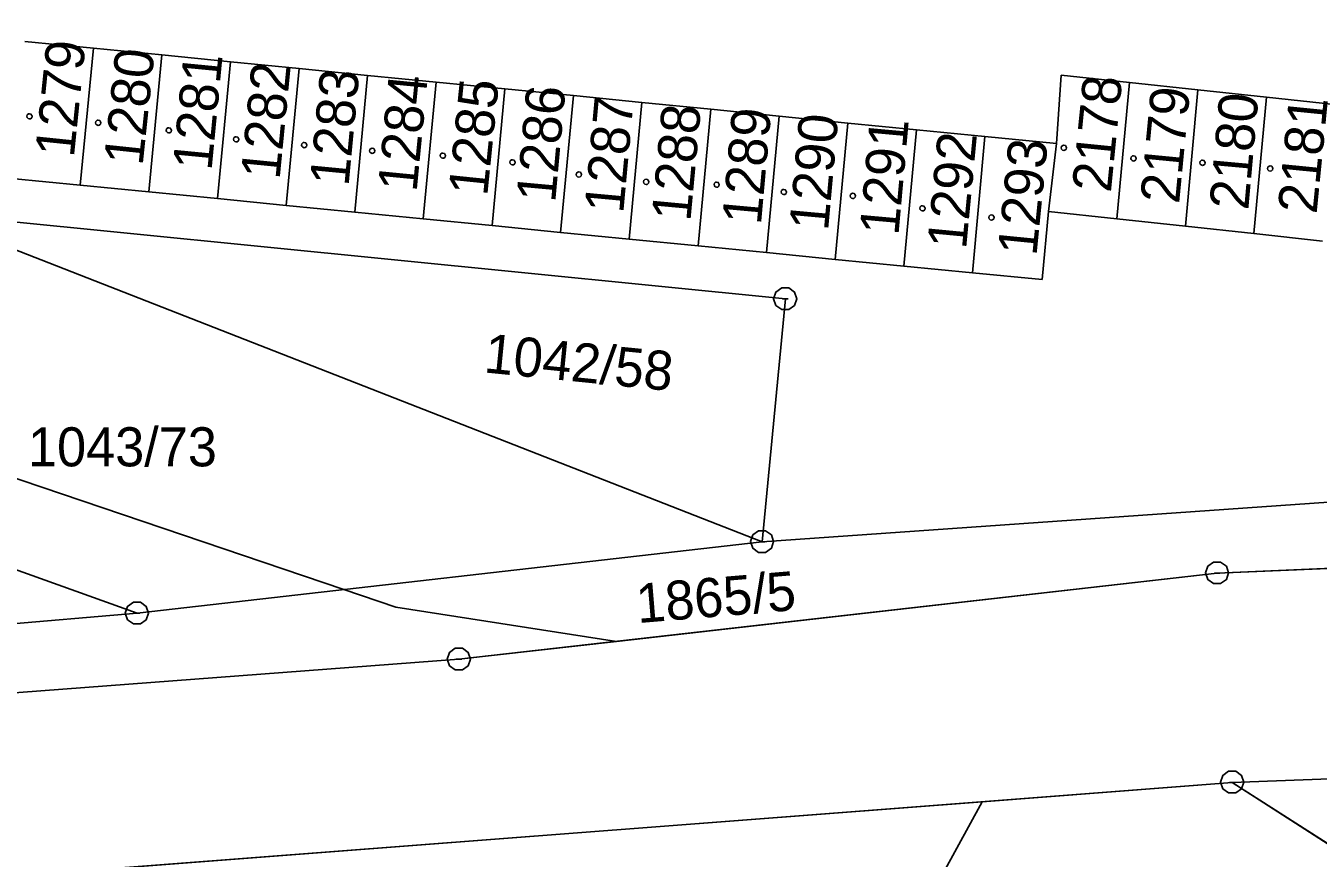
# Model space of a CAD drawing. Extents: x -777309 to -774195, y -1144706 to -1143600.
# Drawn here: x -775189.8 to -775133.6, y -1144462.3 to -1144426.1 of the extents above; entities that cross this region are included whole.
import ezdxf

# ---------------------------------------------------------------- set-up
doc = ezdxf.new("R2010")
doc.units = 0
for name, color, linetype in [('1', 7, 'Continuous'), ('11', 7, 'Continuous'), ('12', 7, 'Continuous'), ('2', 7, 'Continuous'), ('5', 7, 'Continuous'), ('8', 7, 'Continuous')]:
    doc.layers.add(name, color=color, linetype=linetype)

msp = doc.modelspace()

# ---------------------------------------------------------------- linework, layer by layer
at = {"layer": '1'}
for p, q in [((-775186.89, -1144427.09), (-775189.87, -1144426.79)), ((-775186.89, -1144427.09), (-775187.46, -1144433.05)), ((-775183.91, -1144427.38), (-775186.89, -1144427.09)), ((-775184.48, -1144433.34), (-775183.91, -1144427.38)), ((-775180.92, -1144427.68), (-775183.91, -1144427.38)), ((-775180.92, -1144427.68), (-775181.49, -1144433.63)), ((-775177.94, -1144427.97), (-775180.92, -1144427.68)), ((-775178.51, -1144433.92), (-775177.94, -1144427.97)), ((-775174.96, -1144428.27), (-775177.94, -1144427.97)), ((-775174.96, -1144428.27), (-775175.52, -1144434.22)), ((-775171.98, -1144428.56), (-775174.96, -1144428.27)), ((-775172.54, -1144434.51), (-775171.98, -1144428.56)), ((-775168.99, -1144428.86), (-775171.98, -1144428.56)), ((-775145, -1144431.23), (-775144.8, -1144428.26)), ((-775144.8, -1144428.26), (-775141.82, -1144428.58)), ((-775141.82, -1144428.58), (-775142.37, -1144434.51)), ((-775141.82, -1144428.58), (-775138.85, -1144428.9)), ((-775168.99, -1144428.86), (-775169.55, -1144434.8)), ((-775166.01, -1144429.15), (-775168.99, -1144428.86)), ((-775166.57, -1144435.1), (-775166.01, -1144429.15)), ((-775163.03, -1144429.45), (-775166.01, -1144429.15)), ((-775139.39, -1144434.83), (-775138.85, -1144428.9)), ((-775138.85, -1144428.9), (-775135.87, -1144429.22)), ((-775135.87, -1144429.22), (-775136.41, -1144435.15)), ((-775135.87, -1144429.22), (-775132.9, -1144429.54)), ((-775163.03, -1144429.45), (-775163.58, -1144435.39)), ((-775160.04, -1144429.74), (-775163.03, -1144429.45)), ((-775160.59, -1144435.68), (-775160.04, -1144429.74)), ((-775157.06, -1144430.04), (-775160.04, -1144429.74)), ((-775157.06, -1144430.04), (-775157.61, -1144435.97)), ((-775154.08, -1144430.34), (-775157.06, -1144430.04)), ((-775154.62, -1144436.27), (-775154.08, -1144430.34)), ((-775151.09, -1144430.63), (-775154.08, -1144430.34)), ((-775151.09, -1144430.63), (-775151.64, -1144436.56)), ((-775148.11, -1144430.93), (-775151.09, -1144430.63)), ((-775148.65, -1144436.85), (-775148.11, -1144430.93)), ((-775145, -1144431.23), (-775148.11, -1144430.93)), ((-775145.35, -1144434.19), (-775145, -1144431.23)), ((-775190.45, -1144432.75), (-775187.46, -1144433.05)), ((-775187.46, -1144433.05), (-775184.48, -1144433.34)), ((-775184.48, -1144433.34), (-775181.49, -1144433.63)), ((-775181.49, -1144433.63), (-775178.51, -1144433.92)), ((-775194.42, -1144434.23), (-775156.79, -1144437.99)), ((-775157.8, -1144448.55), (-775194.42, -1144434.23)), ((-775178.51, -1144433.92), (-775175.52, -1144434.22)), ((-775175.52, -1144434.22), (-775172.54, -1144434.51)), ((-775145.62, -1144437.15), (-775145.35, -1144434.19)), ((-775142.37, -1144434.51), (-775145.35, -1144434.19)), ((-775172.54, -1144434.51), (-775169.55, -1144434.8)), ((-775169.55, -1144434.8), (-775166.57, -1144435.1)), ((-775139.39, -1144434.83), (-775142.37, -1144434.51)), ((-775136.41, -1144435.15), (-775139.39, -1144434.83)), ((-775166.57, -1144435.1), (-775163.58, -1144435.39)), ((-775163.58, -1144435.39), (-775160.59, -1144435.68)), ((-775133.43, -1144435.48), (-775136.41, -1144435.15)), ((-775160.59, -1144435.68), (-775157.61, -1144435.97)), ((-775157.61, -1144435.97), (-775154.62, -1144436.27)), ((-775154.62, -1144436.27), (-775151.64, -1144436.56)), ((-775151.64, -1144436.56), (-775148.65, -1144436.85)), ((-775148.65, -1144436.85), (-775145.62, -1144437.15)), ((-775156.79, -1144437.99), (-775157.8, -1144448.55)), ((-775157.8, -1144448.55), (-775092.84, -1144444.02)), ((-775184.99, -1144451.66), (-775197.96, -1144447.01)), ((-775088.39, -1144447.82), (-775138.01, -1144449.91)), ((-775184.99, -1144451.66), (-775157.8, -1144448.55)), ((-775138.01, -1144449.91), (-775170.99, -1144453.66)), ((-775212.06, -1144453.97), (-775184.99, -1144451.66)), ((-775170.99, -1144453.66), (-775254.16, -1144459.9)), ((-775096.64, -1144457.51), (-775137.35, -1144459.01)), ((-775137.35, -1144459.01), (-775201.24, -1144463.92)), ((-775137.35, -1144459.01), (-775115.39, -1144473.12))]:
    msp.add_line(p, q, dxfattribs=at)
at = {"layer": '11'}
for p, q in [((-775164.13, -1144452.88), (-775138.01, -1144449.91)), ((-775148.23, -1144459.85), (-775137.35, -1144459.01))]:
    msp.add_line(p, q, dxfattribs=at)
for points in [[(-775666.42, -1144398.43), (-775626.91, -1144413.11), (-775574.03, -1144428.55), (-775529.11, -1144439.07), (-775474.88, -1144449.28), (-775426.17, -1144455.72), (-775417.93, -1144456.81), (-775377.95, -1144459.1), (-775351.35, -1144460.68), (-775341.64, -1144460.83), (-775337.71, -1144460.89), (-775301.48, -1144461.27), (-775254.16, -1144459.9), (-775170.99, -1144453.66), (-775164.13, -1144452.88)], [(-774795.44, -1144408.94), (-774821.85, -1144410.67), (-774824.22, -1144416.24), (-774826.54, -1144421.73), (-774829.24, -1144428.08), (-774832.66, -1144428.33), (-774870.21, -1144431.11), (-774871.96, -1144431.24), (-774890.46, -1144432.61), (-774957.77, -1144437.47), (-775003.31, -1144440.57), (-775006.9, -1144440.82), (-775032.95, -1144440.83), (-775037.63, -1144440.85), (-775036.16, -1144437.94), (-775069.78, -1144440.38), (-775071.04, -1144440.88), (-775088.39, -1144447.82), (-775138.01, -1144449.91)], [(-775230.27, -1144429.21), (-775224.14, -1144434.32), (-775175.99, -1144450.63), (-775173.74, -1144451.39), (-775164.13, -1144452.88)], [(-775493.48, -1144455.3), (-775445.43, -1144461.73), (-775435.74, -1144465.74), (-775366.41, -1144494.44), (-775328.85, -1144510.01), (-775310.26, -1144517.79), (-775294.22, -1144525.5), (-775270.96, -1144536.68), (-775261.18, -1144541.39), (-775253.51, -1144525.7), (-775380, -1144472.53), (-775389.68, -1144468.46), (-775332.79, -1144469.99), (-775289.7, -1144468.96), (-775237.91, -1144466.56), (-775217.76, -1144465.11), (-775204.62, -1144464.16), (-775201.24, -1144463.92), (-775148.23, -1144459.85)], [(-775137.35, -1144459.01), (-775115.39, -1144473.12), (-775113.36, -1144474.42), (-775120.76, -1144481.29), (-775159.15, -1144509.7)], [(-775159.15, -1144509.7), (-775161.04, -1144483.26), (-775148.23, -1144459.85)]]:
    msp.add_lwpolyline(points, dxfattribs=at)
at = {"layer": '12'}
for p, q in [((-775186.89, -1144427.09), (-775189.87, -1144426.79)), ((-775186.89, -1144427.09), (-775187.46, -1144433.05)), ((-775186.89, -1144427.09), (-775187.46, -1144433.05)), ((-775183.91, -1144427.38), (-775186.89, -1144427.09)), ((-775184.48, -1144433.34), (-775183.91, -1144427.38)), ((-775184.48, -1144433.34), (-775183.91, -1144427.38)), ((-775180.92, -1144427.68), (-775183.91, -1144427.38)), ((-775180.92, -1144427.68), (-775181.49, -1144433.63)), ((-775180.92, -1144427.68), (-775181.49, -1144433.63)), ((-775177.94, -1144427.97), (-775180.92, -1144427.68)), ((-775178.51, -1144433.92), (-775177.94, -1144427.97)), ((-775178.51, -1144433.92), (-775177.94, -1144427.97)), ((-775174.96, -1144428.27), (-775177.94, -1144427.97)), ((-775174.96, -1144428.27), (-775175.52, -1144434.22)), ((-775174.96, -1144428.27), (-775175.52, -1144434.22)), ((-775171.98, -1144428.56), (-775174.96, -1144428.27)), ((-775172.54, -1144434.51), (-775171.98, -1144428.56)), ((-775172.54, -1144434.51), (-775171.98, -1144428.56)), ((-775168.99, -1144428.86), (-775171.98, -1144428.56)), ((-775145, -1144431.23), (-775144.8, -1144428.26)), ((-775144.8, -1144428.26), (-775141.82, -1144428.58)), ((-775141.82, -1144428.58), (-775142.37, -1144434.51)), ((-775141.82, -1144428.58), (-775142.37, -1144434.51)), ((-775141.82, -1144428.58), (-775138.85, -1144428.9)), ((-775168.99, -1144428.86), (-775169.55, -1144434.8)), ((-775168.99, -1144428.86), (-775169.55, -1144434.8)), ((-775166.01, -1144429.15), (-775168.99, -1144428.86)), ((-775166.57, -1144435.1), (-775166.01, -1144429.15)), ((-775166.57, -1144435.1), (-775166.01, -1144429.15)), ((-775163.03, -1144429.45), (-775166.01, -1144429.15)), ((-775139.39, -1144434.83), (-775138.85, -1144428.9)), ((-775139.39, -1144434.83), (-775138.85, -1144428.9)), ((-775138.85, -1144428.9), (-775135.87, -1144429.22)), ((-775135.87, -1144429.22), (-775136.41, -1144435.15)), ((-775135.87, -1144429.22), (-775136.41, -1144435.15)), ((-775135.87, -1144429.22), (-775132.9, -1144429.54)), ((-775163.03, -1144429.45), (-775163.58, -1144435.39)), ((-775163.03, -1144429.45), (-775163.58, -1144435.39)), ((-775160.04, -1144429.74), (-775163.03, -1144429.45)), ((-775160.59, -1144435.68), (-775160.04, -1144429.74)), ((-775160.59, -1144435.68), (-775160.04, -1144429.74)), ((-775157.06, -1144430.04), (-775160.04, -1144429.74)), ((-775157.06, -1144430.04), (-775157.61, -1144435.97)), ((-775157.06, -1144430.04), (-775157.61, -1144435.97)), ((-775154.08, -1144430.34), (-775157.06, -1144430.04)), ((-775154.62, -1144436.27), (-775154.08, -1144430.34)), ((-775154.62, -1144436.27), (-775154.08, -1144430.34)), ((-775151.09, -1144430.63), (-775154.08, -1144430.34)), ((-775151.09, -1144430.63), (-775151.64, -1144436.56)), ((-775151.09, -1144430.63), (-775151.64, -1144436.56)), ((-775148.11, -1144430.93), (-775151.09, -1144430.63)), ((-775148.65, -1144436.85), (-775148.11, -1144430.93)), ((-775148.65, -1144436.85), (-775148.11, -1144430.93)), ((-775145, -1144431.23), (-775148.11, -1144430.93)), ((-775145.35, -1144434.19), (-775145, -1144431.23)), ((-775145.35, -1144434.19), (-775145, -1144431.23)), ((-775190.45, -1144432.75), (-775187.46, -1144433.05)), ((-775187.46, -1144433.05), (-775184.48, -1144433.34)), ((-775184.48, -1144433.34), (-775181.49, -1144433.63)), ((-775181.49, -1144433.63), (-775178.51, -1144433.92)), ((-775178.51, -1144433.92), (-775175.52, -1144434.22)), ((-775175.52, -1144434.22), (-775172.54, -1144434.51)), ((-775145.62, -1144437.15), (-775145.35, -1144434.19)), ((-775142.37, -1144434.51), (-775145.35, -1144434.19)), ((-775172.54, -1144434.51), (-775169.55, -1144434.8)), ((-775169.55, -1144434.8), (-775166.57, -1144435.1)), ((-775139.39, -1144434.83), (-775142.37, -1144434.51)), ((-775136.41, -1144435.15), (-775139.39, -1144434.83)), ((-775166.57, -1144435.1), (-775163.58, -1144435.39)), ((-775163.58, -1144435.39), (-775160.59, -1144435.68)), ((-775133.43, -1144435.48), (-775136.41, -1144435.15)), ((-775160.59, -1144435.68), (-775157.61, -1144435.97)), ((-775157.61, -1144435.97), (-775154.62, -1144436.27)), ((-775154.62, -1144436.27), (-775151.64, -1144436.56)), ((-775151.64, -1144436.56), (-775148.65, -1144436.85)), ((-775148.65, -1144436.85), (-775145.62, -1144437.15))]:
    msp.add_line(p, q, dxfattribs=at)
at = {"layer": '5'}
for points in [[(-775189.67, -1144429.936), (-775189.603, -1144429.95), (-775189.569, -1144430.01), (-775189.556, -1144430.05), (-775189.569, -1144430.11), (-775189.623, -1144430.157), (-775189.67, -1144430.164), (-775189.73, -1144430.144), (-775189.771, -1144430.104), (-775189.784, -1144430.05), (-775189.771, -1144429.99), (-775189.717, -1144429.943)], [(-775186.68, -1144430.216), (-775186.613, -1144430.23), (-775186.579, -1144430.29), (-775186.566, -1144430.33), (-775186.579, -1144430.39), (-775186.633, -1144430.437), (-775186.68, -1144430.444), (-775186.74, -1144430.424), (-775186.781, -1144430.384), (-775186.794, -1144430.33), (-775186.781, -1144430.27), (-775186.727, -1144430.223)], [(-775183.61, -1144430.546), (-775183.543, -1144430.559), (-775183.509, -1144430.62), (-775183.496, -1144430.66), (-775183.509, -1144430.72), (-775183.563, -1144430.767), (-775183.61, -1144430.774), (-775183.67, -1144430.754), (-775183.711, -1144430.714), (-775183.724, -1144430.66), (-775183.711, -1144430.6), (-775183.657, -1144430.553)], [(-775180.68, -1144430.936), (-775180.613, -1144430.95), (-775180.579, -1144431.01), (-775180.566, -1144431.05), (-775180.579, -1144431.11), (-775180.633, -1144431.157), (-775180.68, -1144431.164), (-775180.74, -1144431.144), (-775180.781, -1144431.104), (-775180.794, -1144431.05), (-775180.781, -1144430.99), (-775180.727, -1144430.943)], [(-775177.72, -1144431.186), (-775177.653, -1144431.2), (-775177.62, -1144431.26), (-775177.606, -1144431.3), (-775177.62, -1144431.36), (-775177.673, -1144431.407), (-775177.72, -1144431.414), (-775177.78, -1144431.394), (-775177.82, -1144431.354), (-775177.834, -1144431.3), (-775177.82, -1144431.24), (-775177.767, -1144431.193)], [(-775174.76, -1144431.436), (-775174.693, -1144431.45), (-775174.66, -1144431.51), (-775174.646, -1144431.55), (-775174.66, -1144431.61), (-775174.713, -1144431.657), (-775174.76, -1144431.664), (-775174.82, -1144431.644), (-775174.861, -1144431.604), (-775174.874, -1144431.55), (-775174.861, -1144431.49), (-775174.807, -1144431.443)], [(-775144.68, -1144431.306), (-775144.613, -1144431.319), (-775144.579, -1144431.38), (-775144.566, -1144431.42), (-775144.579, -1144431.48), (-775144.633, -1144431.527), (-775144.68, -1144431.534), (-775144.74, -1144431.514), (-775144.781, -1144431.474), (-775144.794, -1144431.42), (-775144.781, -1144431.36), (-775144.727, -1144431.313)], [(-775171.69, -1144431.646), (-775171.623, -1144431.66), (-775171.589, -1144431.72), (-775171.576, -1144431.76), (-775171.589, -1144431.82), (-775171.643, -1144431.867), (-775171.69, -1144431.874), (-775171.75, -1144431.854), (-775171.79, -1144431.814), (-775171.804, -1144431.76), (-775171.79, -1144431.7), (-775171.737, -1144431.653)], [(-775168.66, -1144431.936), (-775168.593, -1144431.95), (-775168.559, -1144432.01), (-775168.546, -1144432.05), (-775168.559, -1144432.11), (-775168.613, -1144432.157), (-775168.66, -1144432.164), (-775168.72, -1144432.144), (-775168.761, -1144432.104), (-775168.774, -1144432.05), (-775168.761, -1144431.99), (-775168.707, -1144431.943)], [(-775141.65, -1144431.766), (-775141.583, -1144431.779), (-775141.549, -1144431.84), (-775141.536, -1144431.88), (-775141.549, -1144431.94), (-775141.603, -1144431.987), (-775141.65, -1144431.994), (-775141.71, -1144431.974), (-775141.751, -1144431.934), (-775141.764, -1144431.88), (-775141.751, -1144431.82), (-775141.697, -1144431.773)], [(-775138.65, -1144431.956), (-775138.583, -1144431.97), (-775138.549, -1144432.03), (-775138.536, -1144432.07), (-775138.549, -1144432.13), (-775138.603, -1144432.177), (-775138.65, -1144432.184), (-775138.71, -1144432.164), (-775138.751, -1144432.124), (-775138.764, -1144432.07), (-775138.751, -1144432.01), (-775138.697, -1144431.963)], [(-775165.77, -1144432.466), (-775165.703, -1144432.48), (-775165.67, -1144432.54), (-775165.656, -1144432.58), (-775165.67, -1144432.64), (-775165.723, -1144432.687), (-775165.77, -1144432.694), (-775165.83, -1144432.674), (-775165.87, -1144432.634), (-775165.884, -1144432.58), (-775165.87, -1144432.52), (-775165.817, -1144432.473)], [(-775135.7, -1144432.206), (-775135.633, -1144432.22), (-775135.6, -1144432.28), (-775135.586, -1144432.32), (-775135.6, -1144432.38), (-775135.653, -1144432.427), (-775135.7, -1144432.434), (-775135.76, -1144432.414), (-775135.8, -1144432.374), (-775135.814, -1144432.32), (-775135.8, -1144432.26), (-775135.747, -1144432.213)], [(-775162.85, -1144432.786), (-775162.783, -1144432.799), (-775162.749, -1144432.86), (-775162.736, -1144432.9), (-775162.749, -1144432.96), (-775162.803, -1144433.007), (-775162.85, -1144433.014), (-775162.91, -1144432.994), (-775162.951, -1144432.954), (-775162.964, -1144432.9), (-775162.951, -1144432.84), (-775162.897, -1144432.793)], [(-775159.78, -1144432.906), (-775159.713, -1144432.92), (-775159.68, -1144432.98), (-775159.666, -1144433.02), (-775159.68, -1144433.08), (-775159.733, -1144433.127), (-775159.78, -1144433.134), (-775159.84, -1144433.114), (-775159.88, -1144433.074), (-775159.894, -1144433.02), (-775159.88, -1144432.96), (-775159.827, -1144432.913)], [(-775156.86, -1144433.226), (-775156.793, -1144433.24), (-775156.759, -1144433.3), (-775156.746, -1144433.34), (-775156.759, -1144433.4), (-775156.813, -1144433.447), (-775156.86, -1144433.454), (-775156.92, -1144433.434), (-775156.961, -1144433.394), (-775156.974, -1144433.34), (-775156.961, -1144433.28), (-775156.907, -1144433.233)], [(-775153.86, -1144433.396), (-775153.793, -1144433.41), (-775153.759, -1144433.47), (-775153.746, -1144433.51), (-775153.759, -1144433.57), (-775153.813, -1144433.617), (-775153.86, -1144433.624), (-775153.92, -1144433.604), (-775153.961, -1144433.564), (-775153.974, -1144433.51), (-775153.961, -1144433.45), (-775153.907, -1144433.403)], [(-775150.83, -1144433.936), (-775150.763, -1144433.95), (-775150.729, -1144434.01), (-775150.716, -1144434.05), (-775150.729, -1144434.11), (-775150.783, -1144434.157), (-775150.83, -1144434.164), (-775150.89, -1144434.144), (-775150.931, -1144434.104), (-775150.944, -1144434.05), (-775150.931, -1144433.99), (-775150.877, -1144433.943)], [(-775147.83, -1144434.336), (-775147.763, -1144434.35), (-775147.729, -1144434.41), (-775147.716, -1144434.45), (-775147.729, -1144434.51), (-775147.783, -1144434.557), (-775147.83, -1144434.564), (-775147.89, -1144434.544), (-775147.931, -1144434.504), (-775147.944, -1144434.45), (-775147.931, -1144434.39), (-775147.877, -1144434.343)]]:
    msp.add_lwpolyline(points, close=True, dxfattribs=at)
at = {"layer": '8'}
for p, q in [((-775156.91, -1144437.99), (-775156.67, -1144437.99)), ((-775157.92, -1144448.55), (-775157.68, -1144448.55)), ((-775138.13, -1144449.91), (-775137.89, -1144449.91)), ((-775185.11, -1144451.66), (-775184.87, -1144451.66)), ((-775171.11, -1144453.66), (-775170.87, -1144453.66)), ((-775137.47, -1144459.01), (-775137.23, -1144459.01))]:
    msp.add_line(p, q, dxfattribs=at)
for points in [[(-775156.64, -1144437.51), (-775156.39, -1144437.69), (-775156.29, -1144437.98), (-775156.39, -1144438.27), (-775156.64, -1144438.45), (-775156.95, -1144438.45), (-775157.2, -1144438.27), (-775157.3, -1144437.98), (-775157.2, -1144437.69), (-775156.95, -1144437.51)], [(-775157.65, -1144448.07), (-775157.4, -1144448.25), (-775157.3, -1144448.54), (-775157.4, -1144448.83), (-775157.65, -1144449.01), (-775157.96, -1144449.01), (-775158.21, -1144448.83), (-775158.31, -1144448.54), (-775158.21, -1144448.25), (-775157.96, -1144448.07)], [(-775137.86, -1144449.43), (-775137.61, -1144449.61), (-775137.51, -1144449.9), (-775137.61, -1144450.19), (-775137.86, -1144450.37), (-775138.17, -1144450.37), (-775138.42, -1144450.19), (-775138.52, -1144449.9), (-775138.42, -1144449.61), (-775138.17, -1144449.43)], [(-775184.84, -1144451.18), (-775184.59, -1144451.36), (-775184.49, -1144451.65), (-775184.59, -1144451.94), (-775184.84, -1144452.12), (-775185.15, -1144452.12), (-775185.4, -1144451.94), (-775185.5, -1144451.65), (-775185.4, -1144451.36), (-775185.15, -1144451.18)], [(-775170.84, -1144453.18), (-775170.59, -1144453.36), (-775170.49, -1144453.65), (-775170.59, -1144453.94), (-775170.84, -1144454.12), (-775171.15, -1144454.12), (-775171.4, -1144453.94), (-775171.5, -1144453.65), (-775171.4, -1144453.36), (-775171.15, -1144453.18)], [(-775137.2, -1144458.53), (-775136.95, -1144458.71), (-775136.85, -1144459), (-775136.95, -1144459.29), (-775137.2, -1144459.47), (-775137.51, -1144459.47), (-775137.76, -1144459.29), (-775137.86, -1144459), (-775137.76, -1144458.71), (-775137.51, -1144458.53)]]:
    msp.add_lwpolyline(points, close=True, dxfattribs=at)

# ---------------------------------------------------------------- texts
at = {"layer": '2'}
for s, rotation, p in [('1279', 84.1102, (-775187.74, -1144431.869)), ('1280', 83.9956, (-775184.749, -1144432.229)), ('1281', 84.5113, (-775181.752, -1144432.439)), ('1282', 84.3967, (-775178.792, -1144432.829)), ('1283', 84.5686, (-775175.793, -1144433.119)), ('1284', 84.454, (-775172.832, -1144433.369)), ('1285', 84.1675, (-775169.76, -1144433.549)), ('2178', 84.2821, (-775142.636, -1144433.394)), ('1286', 84.7978, (-775166.804, -1144433.829)), ('1287', 84.7405, (-775163.844, -1144434.299)), ('2179', 84.5113, (-775139.667, -1144433.884)), ('2180', 84.855, (-775136.659, -1144434.154)), ('1288', 84.6832, (-775160.924, -1144434.649)), ('1289', 84.855, (-775157.855, -1144434.799)), ('2181', 84.3394, (-775133.687, -1144434.324)), ('1290', 84.855, (-775154.935, -1144435.059)), ('1291', 84.855, (-775151.875, -1144435.259)), ('1292', 84.5686, (-775148.933, -1144435.859)), ('1293', 84.3394, (-775145.871, -1144436.149)), ('1042/58', 354.3171, (-775169.938, -1144441.181)), ('1865/5', 4.7555, (-775163.209, -1144452.087))]:
    msp.add_text(s, height=1.7, rotation=rotation, dxfattribs=at).set_placement(p)
msp.add_text('1043/73', height=1.7, dxfattribs=at).set_placement((-775189.734, -1144445.27))

doc.saveas('drawing.dxf')
